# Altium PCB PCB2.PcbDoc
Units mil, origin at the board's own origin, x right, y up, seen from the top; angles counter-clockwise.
Board outline 1300 x 701 mil, 2 copper layers (Top Layer, Bottom Layer); 22 components, 33 nets, 102 pads, 29 vias.
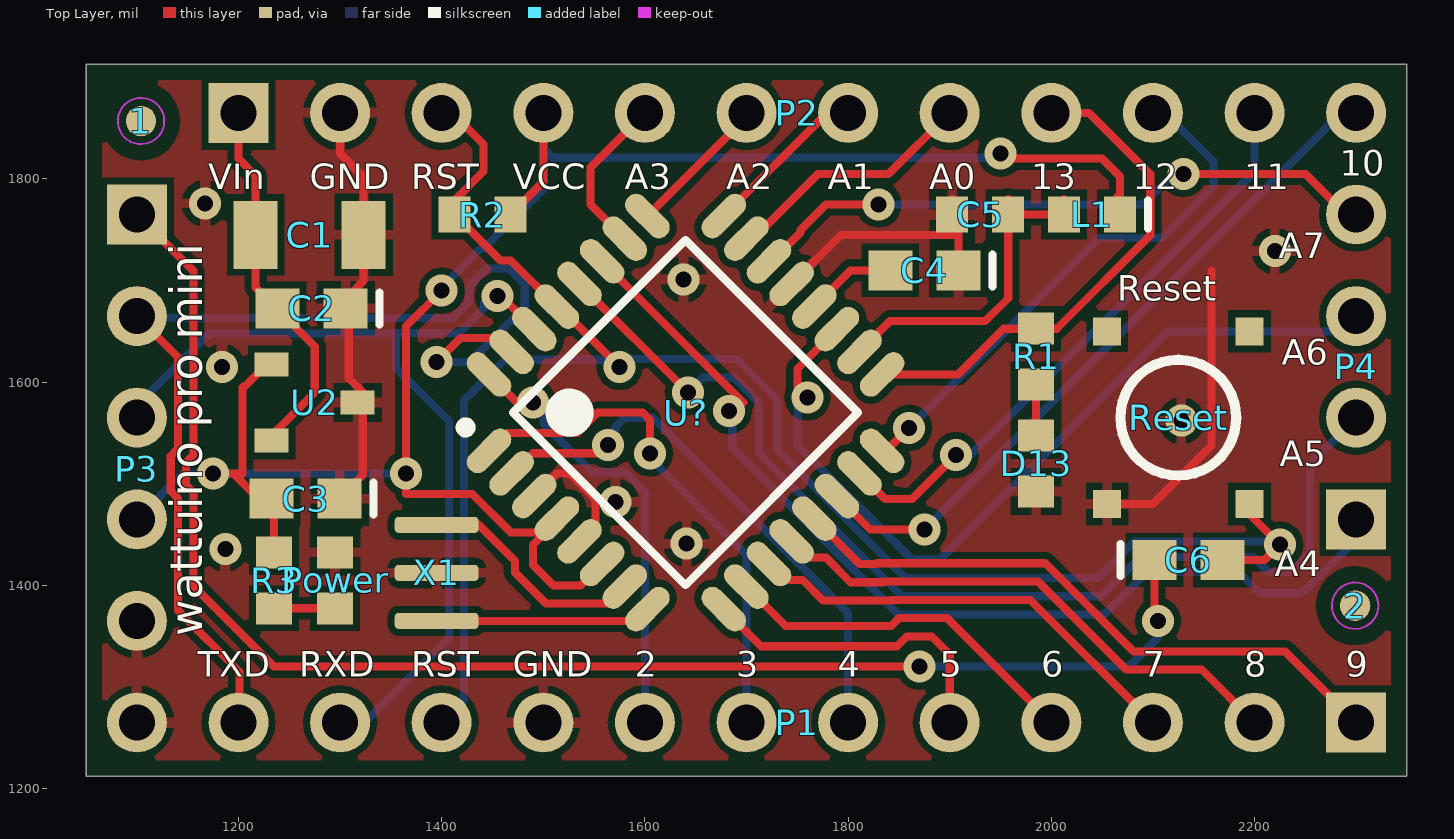
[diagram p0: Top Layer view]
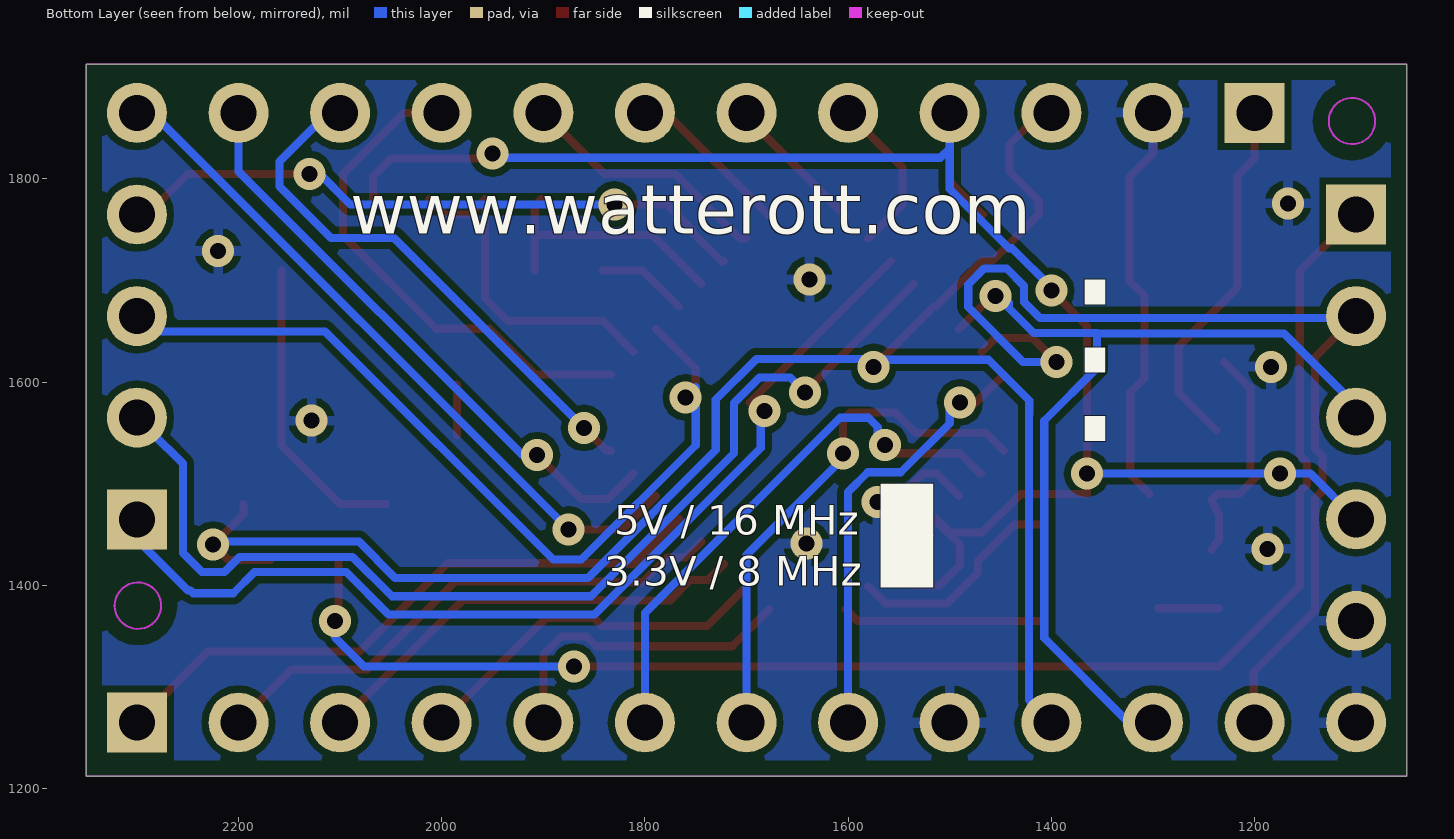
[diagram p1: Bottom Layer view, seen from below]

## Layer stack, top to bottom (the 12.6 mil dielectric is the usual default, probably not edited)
Top Layer: signal copper 1.4
Dielectric: core 12.6, FR-4, Dk 4.8
Bottom Layer: signal copper 1.4

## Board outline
1050,1212 2350,1212 2350,1913 1050,1913

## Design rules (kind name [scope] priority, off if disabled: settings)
Clearance Clearance_1 [InNet('GND') vs OnLayer('Keep-Out Layer')] p1: gap=15
Clearance [All] p2: gap=7
PlaneClearance [All] p1: clearance=10
PolygonConnect [All] p1: connectstyle=Relief reliefconductorwidth=10 reliefentries=4 polygonreliefangle="90 Angle"
RoutingVias [All] p1: holewidth=15.75 width=31.5 viastyle="Through Hole" minholewidth=11.81 minwidth=27.56 maxholewidth=19.68 maxwidth=35.43
SilkscreenOverComponentPads [All] p1: minsilkscreentomaskgap=10
SolderMaskExpansion [All] p1: expansion=4
Width [All] p1: maxlimit=10 minlimit=7 preferedwidth=8
26 further rules are at their usual default settings.

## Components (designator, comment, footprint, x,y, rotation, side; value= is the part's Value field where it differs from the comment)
1 "1" Paser_0,762mm 1104,1857 r270 top
2 "1" Paser_0,762mm 2299,1380 r270 top
C1 "Cap Pol1" C1206 1270,1745 r0 top
C2 "C0603" 0603 1272.06,1672.59 r180 top
C3 "C0603" 0603 1266.06,1485.37 r180 top
C4 "C0603" 0603 1875,1710 r180 top
C5 "C0603" 1608[0603] 1930,1765 r0 top
C6 "C0603" 0603 2135,1425 r0 top
D13 "LED2" 1608[0603] 1985,1520 r270 top
L1 "Inductor" INDC1608L 2040,1765 r180 top
P1 "Header 12" HDR1X12 2300,1265 r180 top
P2 "Header 12" HDR1X12 1200,1865 r0 top
P3 "Header 6H" HDR1X6 1100,1765 r270 top
P4 "Header 4" HDR1X4 2300,1465 r90 top
Power "LED2" 1608[0603] 1295,1405 r90 top
R1 "Res3" 1608[0603] 1985,1625 r90 top
R2 "Res3" 1608[0603] 1440,1765 r180 top
R3 "Res3" 1608[0603] 1235,1405 r90 top
Reset "SW-PB" 4u19182 2195,1480 r180 top
U2 "78L05" SOT23_L 1275,1580 r0 top
U? "ATmega328P-AUR" 32A_L 1640,1570 r45 top
X1 "Resonator" CSTCE 1395,1365 r90 top

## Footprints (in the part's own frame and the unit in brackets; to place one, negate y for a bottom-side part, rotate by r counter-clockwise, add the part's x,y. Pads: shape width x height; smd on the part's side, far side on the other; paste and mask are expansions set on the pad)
4u19182 [mm] "Taster 4ucon 19182"
  rect 0.7x0.7 smd: 1(0,0) 2(0,-4.318) 3(3.556,0) 4(3.556,-4.318)
  silkscreen extent 0.33,-3.61 3.23,-0.71
32A_L [mm] "Thin QFP, 32-Leads, Body 7x7mm, Pitch 0.8mm, IPC High Density"
  oval 1.35x0.55 smd: 1(-4.15,2.8) 2(-4.15,2) 3(-4.15,1.2) 4(-4.15,0.4) 5(-4.15,-0.4) 6(-4.15,-1.2) 7(-4.15,-2) 8(-4.15,-2.8) 17(4.15,-2.8) 18(4.15,-2) 19(4.15,-1.2) 20(4.15,-0.4) 21(4.15,0.4) 22(4.15,1.2) 23(4.15,2) 24(4.15,2.8)
  oval 0.55x1.35 smd: 9(-2.8,-4.15) 10(-2,-4.15) 11(-1.2,-4.15) 12(-0.4,-4.15) 13(0.4,-4.15) 14(1.2,-4.15) 15(2,-4.15) 16(2.8,-4.15) 25(2.8,4.15) 26(2,4.15) 27(1.2,4.15) 28(0.4,4.15) 29(-0.4,4.15) 30(-1.2,4.15) 31(-2,4.15) 32(-2.8,4.15)
  silkscreen extent -4.27,-3.05 3.05,3.75, body extent -3.5,-3.5 3.5,3.5, height 1.2
0603 [mm] "Chip Capacitor; Body 1.6 x 0.8 mm (LxW typ)"
  rect 1.1x1 smd: 1(-0.85,0) 2(0.85,0)
  silkscreen extent -1.7,-0.4 -1.7,0.4
1608[0603] [mm] "Chip Capacitor, Body 1.6x0.8mm, IPC High Density"
  rect 0.8x0.9 smd: 1(-0.7,0) 2(0.7,0)
  body extent -0.87,-0.48 0.87,0.48, height 1.3
C1206 [mm] "Chip Capacitor, Body 3.2x1.6mm, IPC High Density"
  rect 1.1x1.7 smd: 1(-1.35,0) 2(1.35,0)
  body extent -1.7,-0.9 1.7,0.9, height 1.3
CSTCE [mm] "Murata CSTCS Resonator"
  rrect50% 0.4x2.1 smd: 1(0,0) 2(1.2,0) 3(2.4,0)
HDR1X4 [mm] "Connector; Header; 4 Position"
  rect 1.5x1.5 hole 0.9: 1(0,0)
  round 1.5 hole 0.9: 2(2.54,0) 3(5.08,0) 4(7.62,0)
HDR1X6 [mm] "Connector; Header; 6 Position"
  rect 1.5x1.5 hole 0.9: 1(0,0)
  round 1.5 hole 0.9: 2(2.54,0) 3(5.08,0) 4(7.62,0) 5(10.16,0) 6(12.7,0)
HDR1X12 [mm] "Connector; Header; 12 Position"
  rect 1.5x1.5 hole 0.9: 1(0,0)
  round 1.5 hole 0.9: 2(2.54,0) 3(5.08,0) 4(7.62,0) 5(10.16,0) 6(12.7,0) 7(15.24,0) 8(17.78,0) 9(20.32,0) 10(22.86,0) 11(25.4,0) 12(27.94,0)
INDC1608L [mm] "Chip Inductor, Body 1.6x0.8mm, IPC High Density"
  rect 0.8x0.9 smd: 1(-0.7,0) 2(0.7,0)
  silkscreen extent -1.4,-0.35 -1.4,0.35, body extent -0.87,-0.48 0.87,0.48, height 0.55
Paser_0,762mm [mil]
  round 30 smd: 1(0,0)
SOT23_L [mm] "SOT23, 3-Leads, Body 2.9x1.3mm, Pitch 0.95mm, Lead Span 2.3mm - Reverse Pinning, IPC High Density"
  rect 0.85x0.6 smd: 1(1.075,0) 2(-1.075,-0.95) 3(-1.075,0.95)
  body extent -0.7,-1.5 0.7,1.5, height 1.1

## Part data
C1: "Polarized Capacitor (Radial)"
C2 C3 C4 C5 C6: "Ceramic Chip Capacitor - Standard"
D13 Power: "Typical RED, GREEN, YELLOW, AMBER GaAs LED"
P1 P2: "Header, 12-Pin"
P3: "Header, 6-Pin, Right Angle"
P4: "Header, 4-Pin"
R1 R2 R3: "Resistor"
Reset: "Switch"
U2: library part µA78L05ACLP, "Positive-Voltage Regulator"
U?: "8-bit AVR Microcontroller, 32KB Flash, 1KB EEPROM, 2KB SRAM, 32-pin TQFP, Industrial Grade (-40°C to 85°C)"

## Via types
v1: diameter 31.5, hole 15.75, Top Layer to Bottom Layer, tented both sides, 29 vias

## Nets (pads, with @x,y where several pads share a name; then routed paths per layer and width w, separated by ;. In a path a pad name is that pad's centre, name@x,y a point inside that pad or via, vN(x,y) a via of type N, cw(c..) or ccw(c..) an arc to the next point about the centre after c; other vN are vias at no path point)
GND: C1.2 C2.1 C3.1 C4.1 C5.1 D13.2 P1.9 P2.2 P3.5 P3.6 Power.2 Reset.3 U2.1 U?.3 U?.5 U?.21 X1.2 | length 1087.6
  Top Layer w8: P2.2 1300,1825 1323.15,1801.85 1323.15,1699.69 1308.46,1685 1308.46,1603.86 1322.32,1590 1322.32,1508.86 C3.1@1303.46,1490 ; U?.3 1513.19,1510 1526.32,1510 1551.32,1485 1551.32,1459.05 U?.5 ; U?.21 1792.73,1745 1908.46,1745 ; C5.1@1902.44,1780 1908.46,1773.98 1908.46,1745 ; C4.1 1908.46,1745 ; Reset.3 2100,1480 2157.56,1537.56 2157.56,1710
  other v1: 1187,1436 1641,1441 1571,1482 2128,1562 1183.78,1615 1638,1701 2220,1729 1167,1776
NetC4_2: C4.2 U?.20 | length 89.6
  Top Layer w8: U?.20 1802.27,1710 C4.2
NetC5_2: C5.2 L1.2 U?.18 | length 332.9
  Top Layer w8: U?.18 1841.36,1660 1935,1660 1957.56,1682.56 1957.56,1780 1972.56,1765 1997.44,1765 L1.2@2012.44,1780
NetC6_1: C6.1 P3.1 | length 1466.7
  Top Layer w8: P3.1 1155.53,1709.47 1155.53,1528.36 1148.25,1521.08 1148.25,1498.92 1155.53,1491.64 1155.53,1399.47 1235,1320 v1(1870,1320) ; C6.1 2101.54,1368.46 v1(2105,1365)
  Bottom Layer w8: v1(1870,1320) 2076.46,1320 2105,1348.54 v1(2105,1365)
NetC6_2: C6.2 P1.10 P2.3 R2.2 Reset.1 U?.29 | length 1761.4
  Top Layer w8: P2.3 1410.46,1865 1441.28,1834.18 1441.28,1807.54 1412.46,1778.72 R2.2 1457.69,1719.75 1467.98,1719.75 U?.29 1515.6,1674.4 v1(1575,1615) ; C6.2 2210,1425 v1(2225,1440) 2195,1470 Reset.1
  Bottom Layer w8: P1.10 1422,1287 1422,1568.21 1421.75,1568.47 1421.75,1581.75 1462,1622 1568,1622 v1(1575,1615) 1582.75,1622.75 1690.34,1622.75 1730.25,1582.84 1730.25,1533.17 1856.17,1407.25 2045.83,1407.25 2081.57,1443 2222,1443 v1(2225,1440)
NetD13_1: D13.1 R1.1 | length 49.9
  Top Layer w8: D13.1 R1.1
NetP1_1: P1.1 U?.13 | length 617
  Top Layer w8: U?.13 1811.27,1421 1827.11,1421 1827.85,1421.75 1994.16,1421.75 2080.91,1335 2230,1335 P1.1
NetP1_2: P1.2 U?.12 | length 530.1
  Top Layer w8: U?.12 1760.36,1427.37 1778.09,1427.37 1802.46,1403 1834.56,1403 1835.31,1403.75 1986.71,1403.75 2073.46,1317 2148,1317 P1.2
NetP1_3: P1.3 U?.11 | length 443.1
  Top Layer w8: U?.11 1738.09,1405.1 1755.36,1405.1 1775.46,1385 1842.02,1385 1842.77,1385.75 1979.25,1385.75 P1.3
NetP1_4: P1.4 U?.10 | length 362
  Top Layer w8: U?.10 1738.64,1360 1842.47,1360 1850.22,1367.75 1897.25,1367.75 P1.4
NetP1_5: P1.5 U?.9 | length 316
  Top Layer w8: U?.9 1714.1,1340 1847.93,1340 1857.68,1349.75 1882.32,1349.75 1900,1332.07 P1.5
NetP1_6: P1.6 U?.2 | length 547.5
  Top Layer w8: U?.2 1470.15,1510.15 1490,1530 1555.45,1530 v1(1563.5,1538.05)
  Bottom Layer w8: v1(1563.5,1538.05) 1570.81,1545.36 1570.81,1555.81 1580,1565 1607.83,1565 1800,1372.83 P1.6
NetP1_7: P1.7 U?.1 | length 521.3
  Top Layer w8: U?.1 1464.1,1550 1533.38,1550 1544.37,1560.99 1553.38,1570 1597.88,1570 1605,1562.88 v1(1605,1530)
  Bottom Layer w8: v1(1605,1530) 1600,1530 1700,1430 P1.7
NetP1_8: P1.8 U?.32 | length 450.4
  Top Layer w8: U?.32 1474.1,1580 v1(1490,1580) v1@1500,1580
  Bottom Layer w8: v1(1490,1580) 1500,1580 1500,1559.48 1548.18,1511.3 1580.7,1511.3 1600,1492 P1.8
NetP1_11: P1.11 P3.3 U?.30 | length 938.3
  Top Layer w8: v1(1455,1685) 1455,1688.19 U?.30
  Bottom Layer w8: P3.3 1100,1577 1171,1648 1355,1648 ; P1.11 1324,1265 1407,1348 1407,1562 1355,1614 1355,1648 ; v1(1455,1685) 1455,1688.19 1453.19,1690 1441.75,1678.56 1441.75,1672.71 1417.29,1648.25 1355.25,1648.25 1355,1648
NetP1_12: P1.12 P3.2 U?.31 | length 1086.1
  Top Layer w8: P3.2 1140.53,1624.47 1140.53,1534.57 1133.25,1527.29 1133.25,1492.71 1140.53,1485.43 1140.53,1375.22 1200.79,1314.96 1200.79,1265.79 P1.12 ; v1(1395,1620) 1418.54,1643.54 1455.1,1643.54 U?.31
  Bottom Layer w8: P3.2@1100,1663.25 1411.08,1663.25 1426.75,1678.92 1426.75,1694.58 1443.92,1711.75 1466.08,1711.75 1481.75,1696.08 1481.75,1673.92 1427.83,1620 v1(1395,1620)
NetP2_5: P2.5 U?.26 | length 160
  Top Layer w8: U?.26 1546.36,1775 1546.36,1811.36 P2.5
NetP2_6: P2.6 U?.25 | length 141.9
  Top Layer w8: U?.25 1700,1861.06 P2.6
NetP2_7: P2.7 U?.24 | length 164.5
  Top Layer w8: U?.24 1779.1,1865 P2.7
NetP2_8: P2.8 U?.23 | length 251.4
  Top Layer w8: U?.23 1706.66,1741.21 1770.2,1804.75 1839.75,1804.75 P2.8
NetP2_9: P2.9 R1.2 U?.17 | length 503.1
  Top Layer w8: U?.17 1908.04,1607.58 1953.01,1652.56 2005.38,1652.56 2097.31,1744.49 2097.31,1804.76 2037.07,1865 P2.9
NetP2_10: P2.10 U?.16 | length 538.2
  Top Layer w8: U?.16 1837.42,1532.42 v1(1860,1555)
  Bottom Layer w8: v1(1860,1555) 2047,1742 2109.07,1742 2159.75,1792.68 2159.75,1817.32 2112.07,1865 P2.10
NetP2_11: P2.11 U?.15 | length 590.3
  Top Layer w8: U?.15 1836.36,1485 1862.93,1485 v1(1906.04,1528.11)
  Bottom Layer w8: v1(1906.04,1528.11) 1920.63,1528.11 2200,1807.47 P2.11
NetP2_12: P2.12 U?.14 | length 694.5
  Top Layer w8: U?.14 1821.81,1455 v1(1875,1455)
  Bottom Layer w8: v1(1875,1455) 2285,1865 P2.12
NetP4_1: P4.1 U?.27 | length 995.8
  Top Layer w8: U?.27 1696.81,1580 1691.81,1575 1685.96,1575 v1(1682.5,1571.55)
  Bottom Layer w8: v1(1682.5,1571.55) 1685.96,1575 1685.96,1535.04 1849.75,1371.25 2052.25,1371.25 2094,1413 2184.47,1413 2205.22,1392.25 2244.78,1392.25 2247.27,1394.75 2249.75,1394.75 P4.1@2305,1450
NetP4_2: P4.2 U?.28 | length 1068.3
  Top Layer w8: U?.28 v1(1642.27,1590)
  Bottom Layer w8: v1(1642.27,1590) 1657.02,1604.75 1687.13,1604.75 1712.25,1579.63 1712.25,1529.96 1852.96,1389.25 2049.04,1389.25 2087.79,1428 2199.17,1428 2213.92,1413.25 2236.08,1413.25 2254.75,1431.92 2254.75,1519.75 2285,1550 P4.2@2305,1550
NetP4_3: P4.3 U?.19 | length 853.4
  Top Layer w8: v1(1760,1585) 1750,1595 1750,1613.19 U?.19
  Bottom Layer w8: v1(1760,1585) 1750,1595 1750,1537.93 1862.68,1425.25 1890.25,1425.25 2115,1650 P4.3@2305,1650
NetP4_4: P4.4 U?.22 | length 642.7
  Top Layer w8: U?.22 1724.49,1718.94 1753,1747.44 1753,1749.81 1778.19,1775 v1(1830,1775) ; v1(2130,1805) 2250,1805 P4.4@2305,1750
  Bottom Layer w8: v1(1830,1775) 2090,1775 2120,1805 v1(2130,1805)
NetPower_1: Power.1 R3.1 | length 60
  Top Layer w8: R3.1 Power.1
NetU?_7: U?.7 X1.3 | length 216.2
  Top Layer w8: X1.3@1410,1460 1436.1,1460 1472,1424.1 1472,1412.54 1502.54,1382 1563.36,1382 U?.7
NetU?_8: U?.8 X1.1 | length 197.2
  Top Layer w8: X1.1@1410,1365 1559.56,1365 1559.61,1364.95 1578.41,1364.95 1578.46,1365 1590.9,1365 U?.8
V_IN: C1.1 C2.2 P2.1 U2.2 | length 358.9
  Top Layer w8: P2.1 1200,1820 1216.85,1803.15 1216.85,1760 1216.85,1693.34 1275,1635.19 1275,1589.92 U2.2@1237.68,1552.6
VCCS: C3.2 L1.1 P2.4 P3.4 R2.1 R3.2 U2.3 U?.4 U?.6 | length 2023.4
  Top Layer w8: v1(1175,1510) 1204,1510 1204,1595 1205.28,1595 U2.3@1230.18,1619.9 ; 1195,1510 1215,1490 1236.54,1490 1242.44,1484.09 1235,1469.55 1235,1445 R3.2@1242.44,1435 ; v1(1400,1690) 1365,1655 1365,1490 1430,1490 1468.09,1451.91 1499.64,1451.91 U?.4 1513.33,1463.33 1490,1440 1490,1420 1510,1400 1536.81,1400 U?.6 ; R2.1 1500,1797.44 P2.4 ; v1(1950,1825) 1955,1820 2050,1820 2067.56,1802.44 2067.56,1780 L1.1@2065,1782.56
  Bottom Layer w8: P3.4 1145,1510 v1(1175,1510) v1(1365,1510) ; v1(1400,1690) 1400,1692.96 1438.79,1731.75 1441.75,1731.75 1500,1790 1500,1830 ; P2.4 1500,1830 ; v1@1945.1,1815 1940.1,1820 1945,1820 v1@1945.91,1820.91 ; v1(1950,1825) v1@1945.91,1820.91 ; 1500,1830 1509.09,1820.91 v1@1945.91,1820.91
pads on no net: 1.1 2.1 Reset.2 Reset.4

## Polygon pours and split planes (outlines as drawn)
GND on Bottom Layer "Top Layer-No Net" (solid, remove dead copper, pour order 2): 1058,1220 2343,1220 2343,1907 1058,1907
GND on Top Layer "Top Layer-No Net" (solid, remove dead copper, pour order 4): 1058,1220 2342,1220 2342,1907 1058,1907

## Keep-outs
Keep-Out Layer:
  circle w2: c1104,1857 r22.85
  circle w2: c2299,1380 r22.85
  lines w1: 1050,1212 1050,1913 2350,1913 2350,1910 2350,1212 1050,1212

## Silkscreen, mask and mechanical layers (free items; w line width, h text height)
Top Overlay:
  text "10" at 2284,1803 h25
  text "VIn" at 1170,1790 h25
  text "GND" at 1270,1790 h25
  text "RST" at 1370,1790 h25
  text "VCC" at 1470,1790 h25
  text "A3" at 1580,1790 h25
  text "A2" at 1680,1790 h25
  text "A1" at 1780,1790 h25
  text "A0" at 1880,1790 h25
  text "13" at 1980,1790 h25
  text "12" at 2080,1790 h25
  text "11" at 2190,1790 h25
  text "A7" at 2224,1722 h25
  text "Reset" at 2065,1680 h25
  text "A6" at 2227,1617 h25
  text "A5" at 2225,1517 h25
  text "A4" at 2220,1409 h25
  text "wattuino pro mini" at 1175,1350 h55 r90
  text "TXD" at 1160,1310 h25
  text "RXD" at 1260,1310 h25
  text "RST" at 1370,1310 h25
  text "GND" at 1470,1310 h25
  text "2" at 1590,1310 h25
  text "3" at 1690,1310 h25
  text "4" at 1790,1310 h25
  text "5" at 1890,1310 h25
  text "6" at 1990,1310 h25
  text "7" at 2090,1310 h25
  text "8" at 2190,1310 h25
  text "9" at 2290,1310 h25
Bottom Overlay:
  text "www.watterott.com" at 2090,1730 h85
  text "⋮" at 1455,1500 h314.96
  text "■" at 1510,1440 h85
  text "5V / 16 MHz" at 1830,1440 h50
  text "■" at 1510,1390 h85
  text "3.3V / 8 MHz" at 1840,1390 h50
Mechanical 1:
  the board outline again, w1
